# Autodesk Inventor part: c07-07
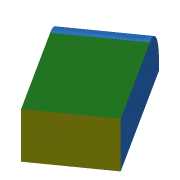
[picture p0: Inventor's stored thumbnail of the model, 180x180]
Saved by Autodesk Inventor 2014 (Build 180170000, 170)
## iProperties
Created: 2013-03
Part Number: c07-07
Material: Generic
Document SubType Name: Modeling
Designer: Thom Tremblay
Density: 1 g/cm^3
Appearance: Cyan
Author: Thom Tremblay
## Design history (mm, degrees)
sketch "Sketch1"
  geometry: L1 (-50, -25)-(50, -25); L2 (50, -25)-(50, 25); L3 (50, 25)-(-50, 25); L4 (-50, 25)-(-50, -25); L5 (-50, -25)-(50, 25); L6 (50, -25)-(-50, 25); 1 further point
  constraints: 12 end point, 2 midpoint, 2 parallel, 1 horizontal, 1 perpendicular
  dimensions: "d0" = 100 distance of L3.end L2.end; "d1" = 50 distance of L2.end L1.end
extrude "Extrusion1" new body sketch "Sketch1" distance "d2" = 30; taper "d3" = 0 deg
fillet "Fillet1" dims "d4" = 24
sketch "Sketch2"
  geometry: C1 r 30 at (-9.032, 94.305); 1 further point
  constraints: 1 centre point
  dimensions: "d11" = 60 diameter of C1
extrude "Extrusion2" new body sketch "Sketch2" distance "d5" = 60; taper "d6" = 0 deg
sketch "Sketch3"
  geometry: C1 r 30 at (0, 0) reference; C2 r 14 at (0, 0); 1 further point
  constraints: 1 centre point, 1 coincident
  dimensions: "d12" = 28 diameter of C2
extrude "Extrusion3" join sketch "Sketch3" distance "d7" = 50; taper "d8" = 0 deg
fillet "Fillet2" dims "d9" = 3, "d10" = 10
node "Block"
node "Pin"
